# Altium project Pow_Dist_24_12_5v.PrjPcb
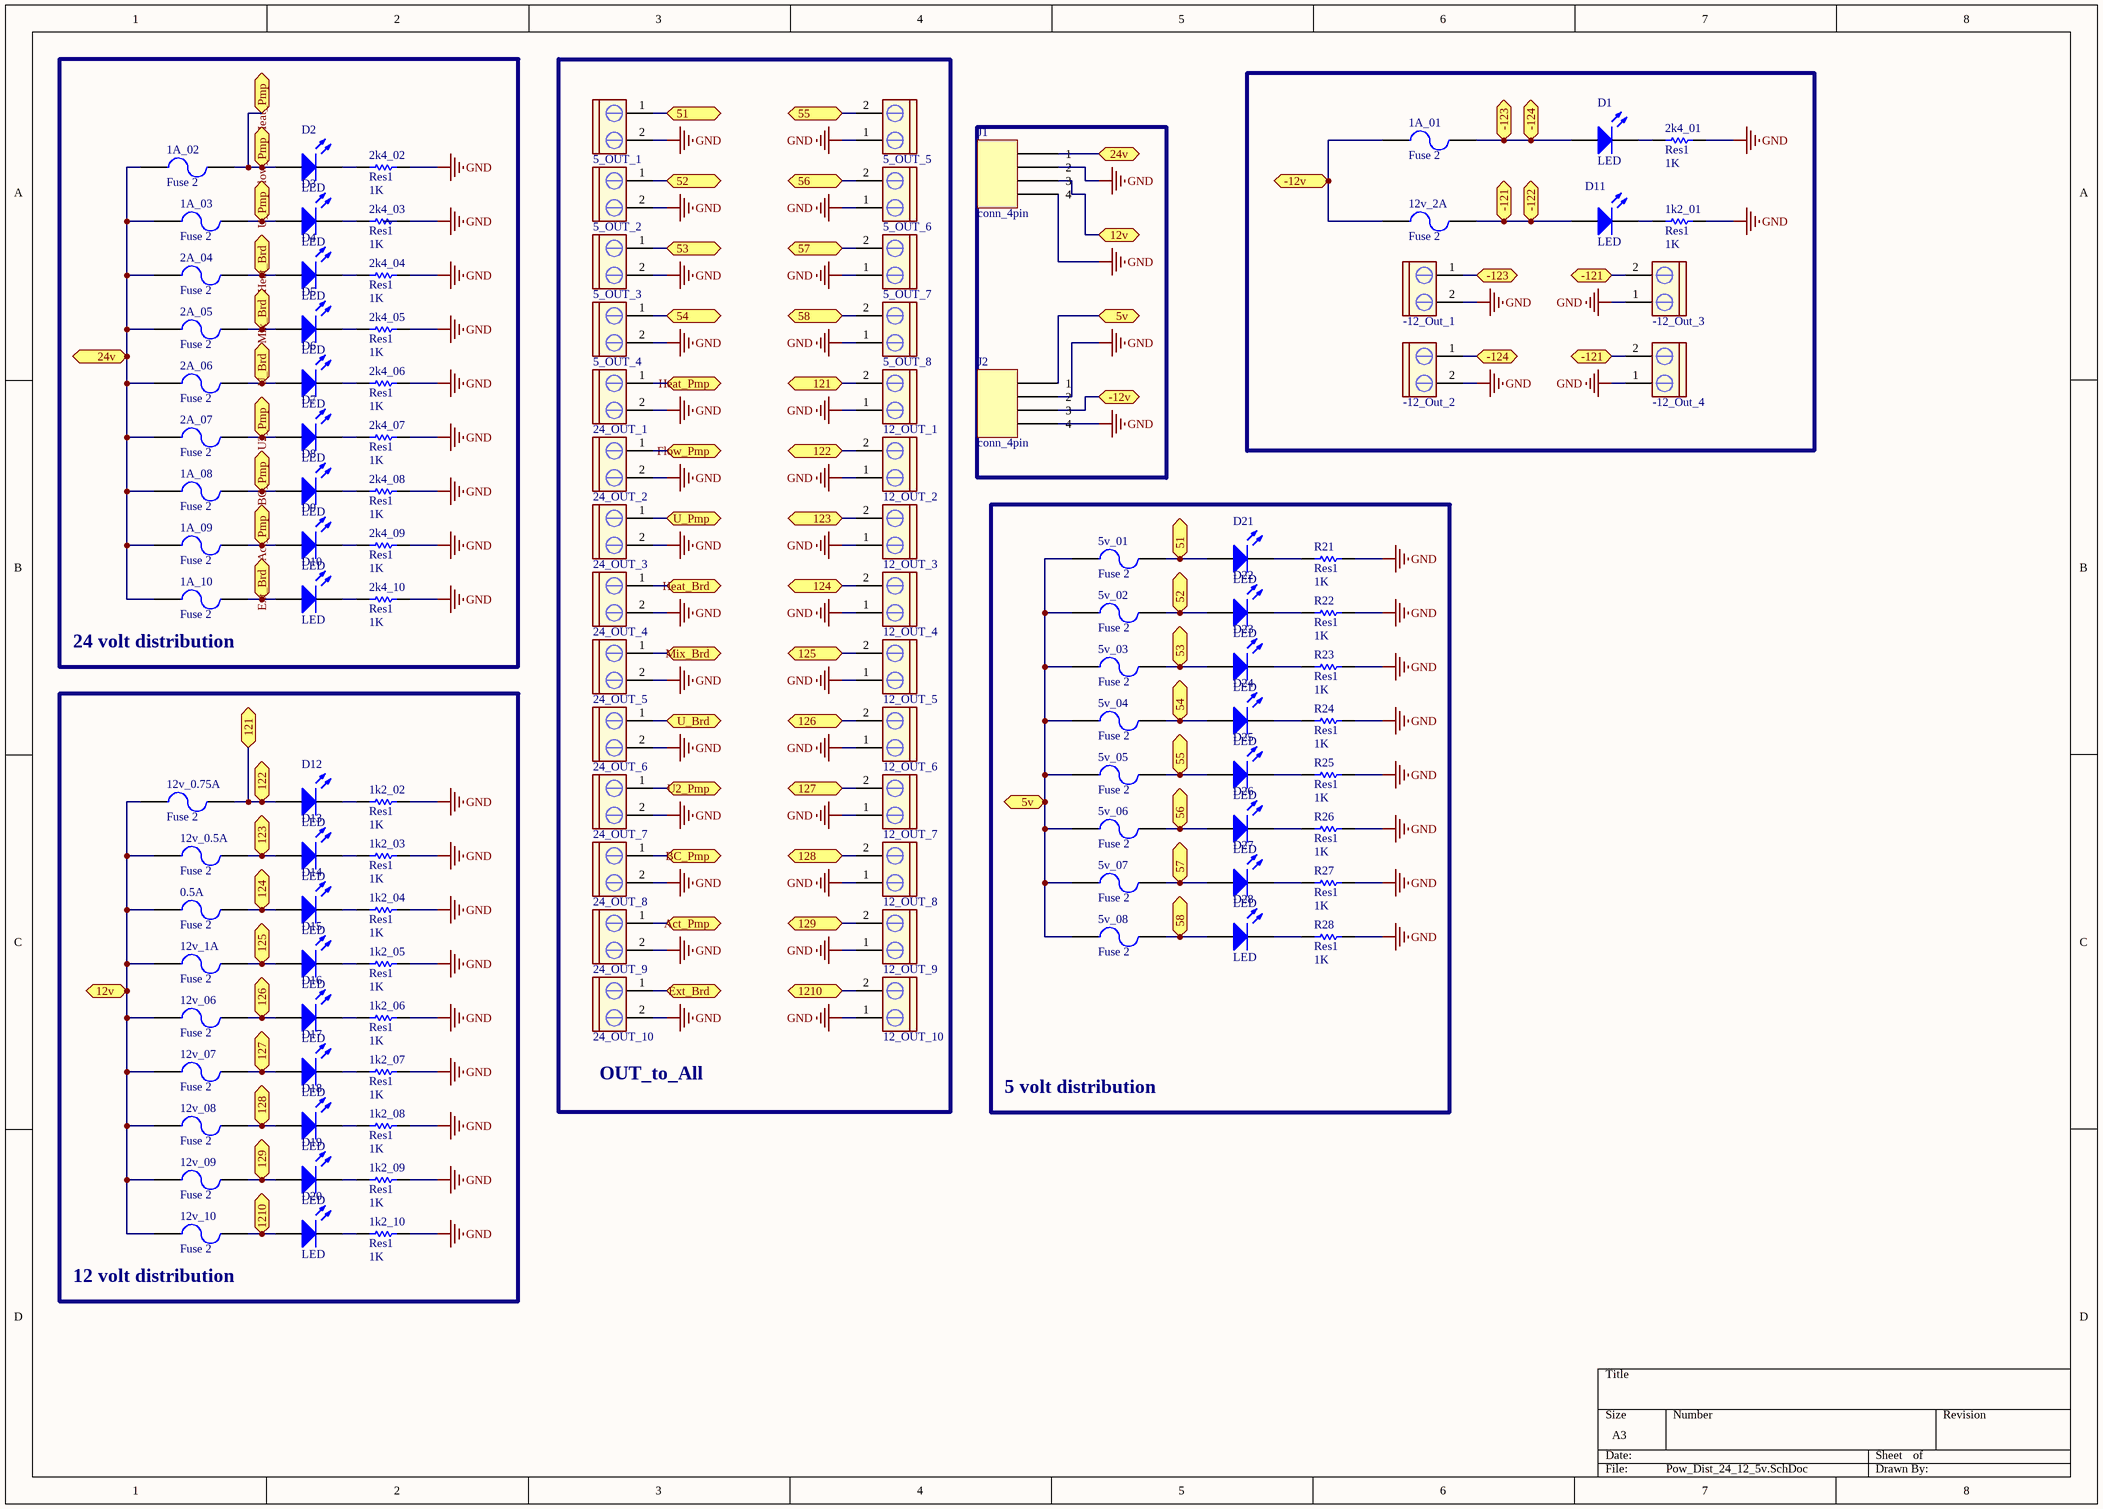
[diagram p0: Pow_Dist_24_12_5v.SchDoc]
2 sheets, 118 parts. Net scope: flat (ports and power ports of the same name join across sheets).
Board file: Pow_Dist_24_12_5v.PcbDoc
Sheets:
  Pow_Dist_24_12_5v.SchDoc
  Pow_Dist_24_12_5v_page2.SchDoc

## Sheet Pow_Dist_24_12_5v.SchDoc
size A3

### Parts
0.5A  Fuse 2  [PCBComponent_1]
1A_01  Fuse 2  [PCBComponent_1]
1A_02  Fuse 2  [PCBComponent_1]
1A_03  Fuse 2  [PCBComponent_1]
1A_08  Fuse 2  [PCBComponent_1]
1A_09  Fuse 2  [PCBComponent_1]
1A_10  Fuse 2  [PCBComponent_1]
1k2_01  Res1  value 1K  [AXIAL-0.3]
1k2_02  Res1  value 1K  [AXIAL-0.3]
1k2_03  Res1  value 1K  [AXIAL-0.3]
1k2_04  Res1  value 1K  [AXIAL-0.3]
1k2_05  Res1  value 1K  [AXIAL-0.3]
1k2_06  Res1  value 1K  [AXIAL-0.3]
1k2_07  Res1  value 1K  [AXIAL-0.3]
1k2_08  Res1  value 1K  [AXIAL-0.3]
1k2_09  Res1  value 1K  [AXIAL-0.3]
1k2_10  Res1  value 1K  [AXIAL-0.3]
2A_04  Fuse 2  [PCBComponent_1]
2A_05  Fuse 2  [PCBComponent_1]
2A_06  Fuse 2  [PCBComponent_1]
2A_07  Fuse 2  [PCBComponent_1]
2k4_01  Res1  value 1K  [AXIAL-0.3]
2k4_02  Res1  value 1K  [AXIAL-0.3]
2k4_03  Res1  value 1K  [AXIAL-0.3]
2k4_04  Res1  value 1K  [AXIAL-0.3]
2k4_05  Res1  value 1K  [AXIAL-0.3]
2k4_06  Res1  value 1K  [AXIAL-0.3]
2k4_07  Res1  value 1K  [AXIAL-0.3]
2k4_08  Res1  value 1K  [AXIAL-0.3]
2k4_09  Res1  value 1K  [AXIAL-0.3]
2k4_10  Res1  value 1K  [AXIAL-0.3]
5_OUT_1  CON2 pin blue  [My_CN2]  (value not drawn)
5_OUT_2  CON2 pin blue  [My_CN2]  (value not drawn)
5_OUT_3  CON2 pin blue  [My_CN2]  (value not drawn)
5_OUT_4  CON2 pin blue  [My_CN2]  (value not drawn)
5_OUT_5  CON2 pin blue  [My_CN2]  (value not drawn)
5_OUT_6  CON2 pin blue  [My_CN2]  (value not drawn)
5_OUT_7  CON2 pin blue  [My_CN2]  (value not drawn)
5_OUT_8  CON2 pin blue  [My_CN2]  (value not drawn)
5v_01  Fuse 2  [PCBComponent_1]
5v_02  Fuse 2  [PCBComponent_1]
5v_03  Fuse 2  [PCBComponent_1]
5v_04  Fuse 2  [PCBComponent_1]
5v_05  Fuse 2  [PCBComponent_1]
5v_06  Fuse 2  [PCBComponent_1]
5v_07  Fuse 2  [PCBComponent_1]
5v_08  Fuse 2  [PCBComponent_1]
12_OUT_1  CON2 pin blue  [My_CN2]  (value not drawn)
12_OUT_2  CON2 pin blue  [My_CN2]  (value not drawn)
12_OUT_3  CON2 pin blue  [My_CN2]  (value not drawn)
12_OUT_4  CON2 pin blue  [My_CN2]  (value not drawn)
12_OUT_5  CON2 pin blue  [My_CN2]  (value not drawn)
12_OUT_6  CON2 pin blue  [My_CN2]  (value not drawn)
12_OUT_7  CON2 pin blue  [My_CN2]  (value not drawn)
12_OUT_8  CON2 pin blue  [My_CN2]  (value not drawn)
12_OUT_9  CON2 pin blue  [My_CN2]  (value not drawn)
12_OUT_10  CON2 pin blue  [My_CN2]  (value not drawn)
12v_0.5A  Fuse 2  [PCBComponent_1]
12v_0.75A  Fuse 2  [PCBComponent_1]
12v_1A  Fuse 2  [PCBComponent_1]
12v_2A  Fuse 2  [PCBComponent_1]
12v_06  Fuse 2  [PCBComponent_1]
12v_07  Fuse 2  [PCBComponent_1]
12v_08  Fuse 2  [PCBComponent_1]
12v_09  Fuse 2  [PCBComponent_1]
12v_10  Fuse 2  [PCBComponent_1]
24_OUT_1  CON2 pin blue  [My_CN2]  (value not drawn)
24_OUT_2  CON2 pin blue  [My_CN2]  (value not drawn)
24_OUT_3  CON2 pin blue  [My_CN2]  (value not drawn)
24_OUT_4  CON2 pin blue  [My_CN2]  (value not drawn)
24_OUT_5  CON2 pin blue  [My_CN2]  (value not drawn)
24_OUT_6  CON2 pin blue  [My_CN2]  (value not drawn)
24_OUT_7  CON2 pin blue  [My_CN2]  (value not drawn)
24_OUT_8  CON2 pin blue  [My_CN2]  (value not drawn)
24_OUT_9  CON2 pin blue  [My_CN2]  (value not drawn)
24_OUT_10  CON2 pin blue  [My_CN2]  (value not drawn)
-12_Out_1  CON2 pin blue  [My_CN2]  (value not drawn)
-12_Out_2  CON2 pin blue  [My_CN2]  (value not drawn)
-12_Out_3  CON2 pin blue  [My_CN2]  (value not drawn)
-12_Out_4  CON2 pin blue  [My_CN2]  (value not drawn)
D1  LED  [My_LED3MM]
D2  LED  [My_LED3MM]
D3  LED  [My_LED3MM]
D4  LED  [My_LED3MM]
D5  LED  [My_LED3MM]
D6  LED  [My_LED3MM]
D7  LED  [My_LED3MM]
D8  LED  [My_LED3MM]
D9  LED  [My_LED3MM]
D10  LED  [My_LED3MM]
D11  LED  [My_LED3MM]
D12  LED  [My_LED3MM]
D13  LED  [My_LED3MM]
D14  LED  [My_LED3MM]
D15  LED  [My_LED3MM]
D16  LED  [My_LED3MM]
D17  LED  [My_LED3MM]
D18  LED  [My_LED3MM]
D19  LED  [My_LED3MM]
D20  LED  [My_LED3MM]
D21  LED  [My_LED3MM]
D22  LED  [My_LED3MM]
D23  LED  [My_LED3MM]
D24  LED  [My_LED3MM]
D25  LED  [My_LED3MM]
D26  LED  [My_LED3MM]
D27  LED  [My_LED3MM]
D28  LED  [My_LED3MM]
J1  conn_4pin  [conn_4pin]
J2  conn_4pin  [conn_4pin]
R21  Res1  value 1K  [AXIAL-0.3]
R22  Res1  value 1K  [AXIAL-0.3]
R23  Res1  value 1K  [AXIAL-0.3]
R24  Res1  value 1K  [AXIAL-0.3]
R25  Res1  value 1K  [AXIAL-0.3]
R26  Res1  value 1K  [AXIAL-0.3]
R27  Res1  value 1K  [AXIAL-0.3]
R28  Res1  value 1K  [AXIAL-0.3]

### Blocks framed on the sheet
24 volt distribution: 1A_02 1A_03 1A_08 1A_09 1A_10 2A_04 2A_05 2A_06 2A_07 2k4_02 2k4_03 2k4_04 2k4_05 2k4_06 2k4_07 2k4_08 2k4_09 2k4_10 D2-D10
OUT_to_All: 5_OUT_1-5_OUT_8 12_OUT_1-12_OUT_10 24_OUT_1-24_OUT_10
5 volt distribution: 5v_01 5v_02 5v_03 5v_04 5v_05 5v_06 5v_07 5v_08 D21-D28 R21-R28
12 volt distribution: 0.5A 1k2_02 1k2_03 1k2_04 1k2_05 1k2_06 1k2_07 1k2_08 1k2_09 1k2_10 12v_0.5A 12v_0.75A 12v_1A 12v_06 12v_07 12v_08 12v_09 12v_10 D12-D20

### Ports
5v, 12v, 24v, 51, 52, 53, 54, 55, 56, 57, 58, 121, 122, 123, 124, 125, 126, 127, 128, 129, 1210, -12v, -121, -122, -123, -124, Act_Pmp, BC_Pmp, Ext_Brd, Flow_Pmp, Heat_Brd, Heat_Pmp, Mix_Brd, U2_Pmp, U_Brd, U_Pmp

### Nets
GND: 1k2_01.2 1k2_02.2 1k2_03.2 1k2_04.2 1k2_05.2 1k2_06.2 1k2_07.2 1k2_08.2 1k2_09.2 1k2_10.2 2k4_01.2 2k4_02.2 2k4_03.2 2k4_04.2 2k4_05.2 2k4_06.2 2k4_07.2 2k4_08.2 2k4_09.2 2k4_10.2 5_OUT_1.2 5_OUT_2.2 5_OUT_3.2 5_OUT_4.2 5_OUT_5.1 5_OUT_6.1 5_OUT_7.1 5_OUT_8.1 12_OUT_1.1 12_OUT_2.1 12_OUT_3.1 12_OUT_4.1 12_OUT_5.1 12_OUT_6.1 12_OUT_7.1 12_OUT_8.1 12_OUT_9.1 12_OUT_10.1 24_OUT_1.2 24_OUT_2.2 24_OUT_3.2 24_OUT_4.2 24_OUT_5.2 24_OUT_6.2 24_OUT_7.2 24_OUT_8.2 24_OUT_9.2 24_OUT_10.2 -12_Out_1.2 -12_Out_2.2 -12_Out_3.1 -12_Out_4.1 R21.2 R22.2 R23.2 R24.2 R25.2 R26.2 R27.2 R28.2
Net0.5A_1: 0.5A.1 12v_0.5A.1 12v_0.75A.1 12v_1A.1 12v_06.1 12v_07.1 12v_08.1 12v_09.1 12v_10.1 ; port 12v
Net0.5A_2: 0.5A.2 12_OUT_4.2 D14.A ; port 124
Net1A_01_1: 1A_01.1 12v_2A.1 ; port -12v
Net1A_01_2: 1A_01.2 -12_Out_1.1 -12_Out_2.1 D1.A ; port -123, port -124
Net1A_02_1: 1A_02.1 1A_03.1 1A_08.1 1A_09.1 1A_10.1 2A_04.1 2A_05.1 2A_06.1 2A_07.1 ; port 24v
Net1A_02_2: 1A_02.2 24_OUT_1.1 24_OUT_2.1 D2.A ; port Heat_Pmp, port Flow_Pmp
Net1A_03_2: 1A_03.2 24_OUT_3.1 D3.A ; port U_Pmp
Net1A_08_2: 1A_08.2 24_OUT_8.1 D8.A ; port BC_Pmp
Net1A_09_2: 1A_09.2 24_OUT_9.1 D9.A ; port Act_Pmp
Net1A_10_2: 1A_10.2 24_OUT_10.1 D10.A ; port Ext_Brd
Net1k2_01_1: 1k2_01.1 D11.K
Net1k2_02_1: 1k2_02.1 D12.K
Net1k2_03_1: 1k2_03.1 D13.K
Net1k2_04_1: 1k2_04.1 D14.K
Net1k2_05_1: 1k2_05.1 D15.K
Net1k2_06_1: 1k2_06.1 D16.K
Net1k2_07_1: 1k2_07.1 D17.K
Net1k2_08_1: 1k2_08.1 D18.K
Net1k2_09_1: 1k2_09.1 D19.K
Net1k2_10_1: 1k2_10.1 D20.K
Net2A_04_2: 2A_04.2 24_OUT_4.1 D4.A ; port Heat_Brd
Net2A_05_2: 2A_05.2 24_OUT_5.1 D5.A ; port Mix_Brd
Net2A_06_2: 2A_06.2 24_OUT_6.1 D6.A ; port U_Brd
Net2A_07_2: 2A_07.2 24_OUT_7.1 D7.A ; port U2_Pmp
Net2k4_01_1: 2k4_01.1 D1.K
Net2k4_02_1: 2k4_02.1 D2.K
Net2k4_03_1: 2k4_03.1 D3.K
Net2k4_04_1: 2k4_04.1 D4.K
Net2k4_05_1: 2k4_05.1 D5.K
Net2k4_06_1: 2k4_06.1 D6.K
Net2k4_07_1: 2k4_07.1 D7.K
Net2k4_08_1: 2k4_08.1 D8.K
Net2k4_09_1: 2k4_09.1 D9.K
Net2k4_10_1: 2k4_10.1 D10.K
Net5_OUT_1_1: 5_OUT_1.1 5v_01.2 D21.A ; port 51
Net5_OUT_2_1: 5_OUT_2.1 5v_02.2 D22.A ; port 52
Net5_OUT_3_1: 5_OUT_3.1 5v_03.2 D23.A ; port 53
Net5_OUT_4_1: 5_OUT_4.1 5v_04.2 D24.A ; port 54
Net5_OUT_5_2: 5_OUT_5.2 5v_05.2 D25.A ; port 55
Net5_OUT_6_2: 5_OUT_6.2 5v_06.2 D26.A ; port 56
Net5_OUT_7_2: 5_OUT_7.2 5v_07.2 D27.A ; port 57
Net5_OUT_8_2: 5_OUT_8.2 5v_08.2 D28.A ; port 58
Net5v_01_1: 5v_01.1 5v_02.1 5v_03.1 5v_04.1 5v_05.1 5v_06.1 5v_07.1 5v_08.1 ; port 5v
Net12_OUT_1_2: 12_OUT_1.2 12_OUT_2.2 12v_0.75A.2 D12.A ; port 121, port 122
Net12_OUT_3_2: 12_OUT_3.2 12v_0.5A.2 D13.A ; port 123
Net12_OUT_5_2: 12_OUT_5.2 12v_1A.2 D15.A ; port 125
Net12_OUT_6_2: 12_OUT_6.2 12v_06.2 D16.A ; port 126
Net12_OUT_7_2: 12_OUT_7.2 12v_07.2 D17.A ; port 127
Net12_OUT_8_2: 12_OUT_8.2 12v_08.2 D18.A ; port 128
Net12_OUT_9_2: 12_OUT_9.2 12v_09.2 D19.A ; port 129
Net12_OUT_10_2: 12_OUT_10.2 12v_10.2 D20.A ; port 1210
Net12v_2A_2: 12v_2A.2 -12_Out_3.2 -12_Out_4.2 D11.A ; port -121, port -122
NetD21_K: D21.K R21.1
NetD22_K: D22.K R22.1
NetD23_K: D23.K R23.1
NetD24_K: D24.K R24.1
NetD25_K: D25.K R25.1
NetD26_K: D26.K R26.1
NetD27_K: D27.K R27.1
NetD28_K: D28.K R28.1

Not connected (* = marked no-connect by the designer): J1 1 2 3 4; J2 1 2 3 4

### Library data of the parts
0.5A 1A_01 1A_02 1A_03 1A_08 1A_09 1A_10 2A_04 2A_05 2A_06 2A_07 5v_01 5v_02 5v_03 5v_04 5v_05 5v_06 5v_07 5v_08 12v_0.5A 12v_0.75A 12v_1A 12v_2A 12v_06 12v_07 12v_08 12v_09 12v_10 = Fuse 2: Fuse
1k2_01 1k2_02 1k2_03 1k2_04 1k2_05 1k2_06 1k2_07 1k2_08 1k2_09 1k2_10 2k4_01 2k4_02 2k4_03 2k4_04 2k4_05 2k4_06 2k4_07 2k4_08 2k4_09 2k4_10 R21-R28 = Res1: Resistor
5_OUT_1-5_OUT_8 12_OUT_1-12_OUT_10 24_OUT_1-24_OUT_10 -12_Out_1--12_Out_4 = CON2 pin blue: Connector blue screw
D1-D28 = LED: Typical INFRARED GaAs LED

## Sheet Pow_Dist_24_12_5v_page2.SchDoc
size A4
